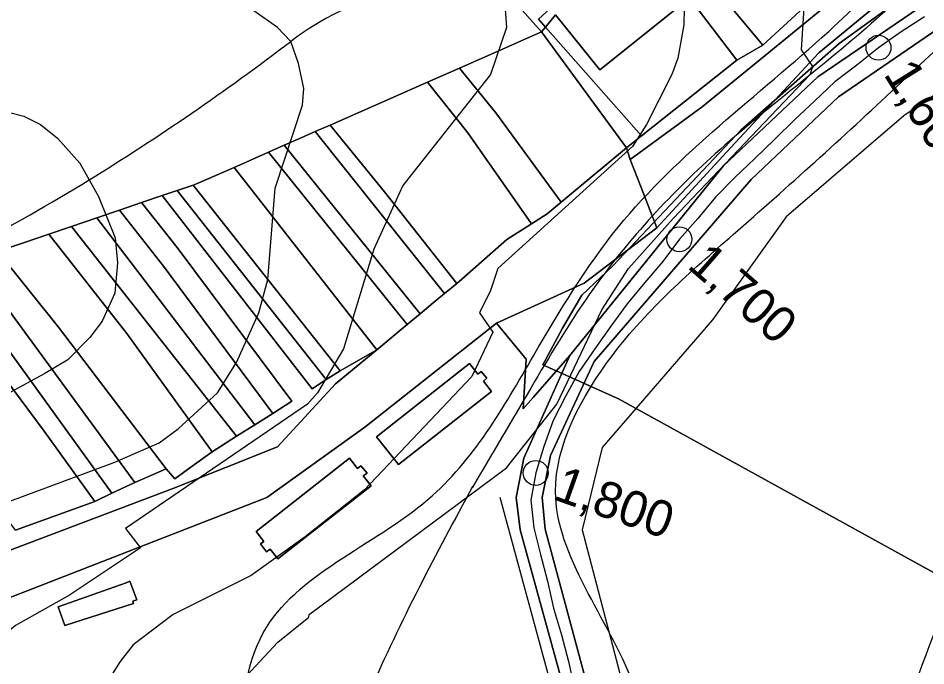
# Model space of a CAD drawing. Extents: x -510989 to -501240, y -1184665 to -1176089.
# Drawn here: x -504942 to -504614, y -1181176.6 to -1180942.6 of the extents above; entities that cross this region are included whole.
import ezdxf

# ---------------------------------------------------------------- set-up
doc = ezdxf.new("R2010")
doc.units = 0
for name, color, linetype in [('lesni_pozemek', 7, 'Continuous'), ('NAVRH_revitalizace_toku', 7, 'Continuous'), ('NAVRH_rozvodnice', 7, 'Continuous'), ('orna_puda', 7, 'Continuous'), ('ostatni_plocha_x_manipulacni_plocha', 7, 'Continuous'), ('ostatni_plocha_x_neplodna_puda', 7, 'Continuous'), ('ostatni_plocha_x_silnice', 7, 'Continuous'), ('ostatni_plocha_x_sportoviste_a_rekr_plocha', 7, 'Continuous'), ('STAV_USES', 7, 'Continuous'), ('STAV_zaplavove_uzemi', 7, 'Continuous'), ('trasovani_toku', 7, 'Continuous'), ('vodni_plocha_x_vodni_tok_v_koryt_prir_n_upr', 7, 'Continuous'), ('vrstevnice_01', 7, 'Continuous'), ('vrstevnice_02', 7, 'Continuous'), ('zastavena_plocha_a_nadvori', 7, 'Continuous')]:
    doc.layers.add(name, color=color, linetype=linetype)

msp = doc.modelspace()

# ---------------------------------------------------------------- linework, layer by layer
at = {"layer": 'lesni_pozemek'}
msp.add_lwpolyline([(-504775.02, -1180922.63), (-504752.9, -1180947.58), (-504771.38, -1180955.72), (-504782.54, -1180960.64), (-504794.06, -1180965.71), (-504829.23, -1180981.2), (-504834.63, -1180983.58), (-504839.79, -1180985.85), (-504845.84, -1180988.52), (-504851.49, -1180991.01), (-504863.93, -1180996.49), (-504877.51, -1181002.47), (-504878.78, -1181002.9), (-504884.56, -1181004.86), (-504890, -1181006.71), (-504897.47, -1181009.24), (-504905.42, -1181011.95), (-504913.53, -1181014.7), (-504922.73, -1181017.82), (-504930.97, -1181020.62), (-504940.12, -1181023.73), (-504949.52, -1181026.92)], dxfattribs=at)
at = {"layer": 'NAVRH_revitalizace_toku'}
for points in [[(-504182.04, -1180792.04), (-504204.87, -1180813.12), (-504441.3, -1180893.49), (-504535.64, -1180920.73), (-504547.6, -1180927.38), (-504622.01, -1180977.87), (-504664.53, -1181014.41), (-504691.11, -1181051.62), (-504730.92, -1181097.66), (-504738.16, -1181127.41), (-504718.87, -1181201.36), (-504687.51, -1181317.93), (-504646.6, -1181475.99), (-504595.04, -1181660.81)], [(-504619.38, -1181665.94), (-504652.45, -1181546.29), (-504699.14, -1181368.28), (-504767.85, -1181115.82)]]:
    msp.add_lwpolyline(points, dxfattribs=at)
at = {"layer": 'NAVRH_rozvodnice'}
for centre, radius, start, end in [((-504781.18, -1181032.78), 102.82, 81.8427, 127.3105), ((-505385.87, -1180239.31), 894.79, 301.65308, 307.31051), ((-505269.53, -1180428.03), 673.1, 293.18985, 301.65308)]:
    msp.add_arc(centre, radius, start, end, dxfattribs=at)
at = {"layer": 'orna_puda'}
for points in [[(-504609.62, -1181654.37), (-504714.66, -1181264.33), (-504714.68, -1181264.25), (-504716.76, -1181256.52), (-504751.58, -1181127.22), (-504752.67, -1181115.82), (-504749.63, -1181100.59), (-504733.91, -1181066.63), (-504677.14, -1181000.88), (-504645.58, -1180971.03), (-504557.05, -1180910.28)], [(-504942.94, -1181127.57), (-504914.26, -1181117.19), (-504908.15, -1181114.19), (-504899.88, -1181110.39), (-504888.48, -1181105.35), (-504885.33, -1181108.96), (-504879.16, -1181104.4), (-504871.86, -1181099.28), (-504863.09, -1181093.58), (-504856.53, -1181089.46), (-504850.02, -1181085.38), (-504843.15, -1181080.96), (-504884.52, -1181025.4), (-504897.47, -1181009.24), (-504890, -1181006.71), (-504835.74, -1181076.52), (-504830.68, -1181073.09), (-504825.69, -1181070.01), (-504812.44, -1181062.36), (-504827.33, -1181074.66), (-504848.34, -1181097.46), (-504885.76, -1181112.45), (-504945.87, -1181135.16)]]:
    msp.add_lwpolyline(points, dxfattribs=at)
for points in [[(-504752.9, -1180947.58), (-504722.23, -1180989.44), (-504735.7, -1181000.67), (-504745.74, -1181009.04), (-504769.45, -1180976.84), (-504782.54, -1180960.64), (-504771.38, -1180955.72)], [(-504782.54, -1180960.64), (-504769.45, -1180976.84), (-504745.74, -1181009.04), (-504750.89, -1181013.33), (-504756.51, -1181016.88), (-504779.57, -1180983.97), (-504794.06, -1180965.71)], [(-504794.06, -1180965.71), (-504779.57, -1180983.97), (-504756.51, -1181016.88), (-504765.42, -1181022.51), (-504781.63, -1181036.9), (-504783.51, -1181038.45), (-504809.57, -1181005.36), (-504829.23, -1180981.2)], [(-504829.23, -1180981.2), (-504809.57, -1181005.36), (-504783.51, -1181038.45), (-504787.94, -1181042.11), (-504834.63, -1180983.58)], [(-504834.63, -1180983.58), (-504787.94, -1181042.11), (-504791.99, -1181045.46), (-504796.71, -1181049.36), (-504845.84, -1180988.52), (-504839.79, -1180985.85)], [(-504845.84, -1180988.52), (-504796.71, -1181049.36), (-504801.38, -1181053.22), (-504851.49, -1180991.01)], [(-504851.49, -1180991.01), (-504801.38, -1181053.22), (-504812.44, -1181062.36), (-504863.93, -1180996.49)], [(-504863.93, -1180996.49), (-504812.44, -1181062.36), (-504825.69, -1181070.01), (-504878.78, -1181002.9), (-504877.51, -1181002.47)], [(-504884.56, -1181004.86), (-504830.68, -1181073.09), (-504835.74, -1181076.52), (-504890, -1181006.71)], [(-504878.78, -1181002.9), (-504825.69, -1181070.01), (-504830.68, -1181073.09), (-504884.56, -1181004.86)], [(-504897.47, -1181009.24), (-504884.52, -1181025.4), (-504843.15, -1181080.96), (-504850.02, -1181085.38), (-504889.51, -1181032.24), (-504905.42, -1181011.95)], [(-504913.53, -1181014.7), (-504856.53, -1181089.46), (-504863.09, -1181093.58), (-504922.73, -1181017.82)], [(-504905.42, -1181011.95), (-504889.51, -1181032.24), (-504850.02, -1181085.38), (-504856.53, -1181089.46), (-504913.53, -1181014.7)], [(-504922.73, -1181017.82), (-504863.09, -1181093.58), (-504871.86, -1181099.28), (-504902.76, -1181056.48), (-504930.97, -1181020.62)], [(-504930.97, -1181020.62), (-504902.76, -1181056.48), (-504871.86, -1181099.28), (-504879.16, -1181104.4), (-504885.33, -1181108.96), (-504888.48, -1181105.35), (-504927.37, -1181054.18), (-504949.52, -1181026.92), (-504940.12, -1181023.73)], [(-504949.52, -1181026.92), (-504927.37, -1181054.18), (-504888.48, -1181105.35), (-504899.88, -1181110.39), (-504958.78, -1181030.06)], [(-504958.78, -1181030.06), (-504899.88, -1181110.39), (-504908.15, -1181114.19), (-504964.75, -1181035.96)], [(-504964.75, -1181035.96), (-504908.15, -1181114.19), (-504914.26, -1181117.19), (-504932.57, -1181091.77), (-504970.16, -1181041.3)], [(-504970.16, -1181041.3), (-504932.57, -1181091.77), (-504914.26, -1181117.19), (-504942.94, -1181127.57), (-504991.43, -1181062.3)]]:
    msp.add_lwpolyline(points, close=True, dxfattribs=at)
at = {"layer": 'ostatni_plocha_x_manipulacni_plocha'}
msp.add_lwpolyline([(-504669.28, -1180908.4), (-504646.56, -1180892.33), (-504625.33, -1180910.8), (-504628.44, -1180912.7), (-504642.21, -1180924.36), (-504649.15, -1180930.38), (-504672.94, -1180952.33), (-504688.81, -1180933.14), (-504690.04, -1180930.4), (-504690.56, -1180927.53), (-504689.67, -1180924.68), (-504688.1, -1180922.19), (-504674.05, -1180911.16)], close=True, dxfattribs=at)
msp.add_lwpolyline([(-504688.81, -1180933.14), (-504672.94, -1180952.33), (-504682.35, -1180957.74), (-504699.48, -1180935.25), (-504731.88, -1180961.27), (-504747.81, -1180941.41), (-504751.48, -1180945.85), (-504754, -1180943), (-504718, -1180910)], dxfattribs=at)
at = {"layer": 'ostatni_plocha_x_neplodna_puda'}
msp.add_lwpolyline([(-504582.6, -1180900.93), (-504574.16, -1180900.62), (-504566.19, -1180904.56), (-504653.08, -1180963.75), (-504687.23, -1180996.05), (-504742.72, -1181064.52), (-504755.9, -1181079.67), (-504759.48, -1181083.79), (-504758.44, -1181065.74), (-504769.19, -1181052.84), (-504737.43, -1181038.27), (-504711.26, -1181018.31), (-504686.07, -1180991.03), (-504652.66, -1180955.07), (-504600.25, -1180911.88)], close=True, dxfattribs=at)
at = {"layer": 'ostatni_plocha_x_silnice'}
for points in [[(-504600.25, -1180911.88), (-504652.66, -1180955.07), (-504686.07, -1180991.03), (-504711.26, -1181018.31), (-504716.94, -1181003.71), (-504719.55, -1180997), (-504720.83, -1180993.69), (-504694.88, -1180974.6), (-504670.77, -1180954.95), (-504614.89, -1180909.19), (-504613.27, -1180908.14), (-504617.64, -1180907.65), (-504616.22, -1180905.23), (-504600.67, -1180895.84)], [(-504945.87, -1181135.16), (-504885.76, -1181112.45), (-504848.34, -1181097.46), (-504827.33, -1181074.66), (-504812.44, -1181062.36), (-504801.38, -1181053.22), (-504796.71, -1181049.36), (-504791.99, -1181045.46), (-504787.94, -1181042.11), (-504783.51, -1181038.45), (-504781.63, -1181036.9), (-504765.42, -1181022.51), (-504756.51, -1181016.88), (-504750.89, -1181013.33), (-504745.74, -1181009.04), (-504735.7, -1181000.67), (-504722.23, -1180989.44), (-504720.83, -1180993.69), (-504719.55, -1180997), (-504716.94, -1181003.71), (-504711.26, -1181018.31), (-504737.43, -1181038.27), (-504769.19, -1181052.84), (-504816.79, -1181090.4), (-504852.19, -1181115.81), (-504959.56, -1181157.6)]]:
    msp.add_lwpolyline(points, dxfattribs=at)
at = {"layer": 'ostatni_plocha_x_sportoviste_a_rekr_plocha'}
for points in [[(-504808, -1180882.51), (-504725, -1180870), (-504718, -1180910), (-504754, -1180943), (-504751.48, -1180945.85), (-504752.9, -1180947.58), (-504775.02, -1180922.63), (-504813.81, -1180883.39)], [(-504616.22, -1180905.23), (-504617.64, -1180907.65), (-504613.27, -1180908.14), (-504614.89, -1180909.19), (-504670.77, -1180954.95), (-504694.88, -1180974.6), (-504720.83, -1180993.69), (-504722.23, -1180989.44), (-504716.78, -1180985.11), (-504682.35, -1180957.74), (-504672.94, -1180952.33), (-504649.15, -1180930.38), (-504642.21, -1180924.36), (-504628.44, -1180912.7), (-504625.33, -1180910.8)], [(-504775.91, -1181071.15), (-504778.88, -1181067.35), (-504812.53, -1181093.83), (-504804.63, -1181103.82), (-504771, -1181077.43), (-504773.91, -1181073.71), (-504772.62, -1181072.71), (-504774.74, -1181070.23)], [(-504818.23, -1181104.36), (-504819.38, -1181105.25), (-504822.22, -1181101.56), (-504856, -1181127.99), (-504853.24, -1181131.6), (-504854.48, -1181132.56), (-504852.28, -1181135.34), (-504850.98, -1181134.47), (-504848.17, -1181137.97), (-504814.5, -1181111.6), (-504817.28, -1181107.99), (-504815.94, -1181106.96)], [(-504901.63, -1181145.94), (-504903.01, -1181146.58), (-504927.59, -1181155.21), (-504925.18, -1181161.97), (-504900.33, -1181154.06), (-504900.6, -1181153.27), (-504899.1, -1181152.68)]]:
    msp.add_lwpolyline(points, close=True, dxfattribs=at)
msp.add_lwpolyline([(-504959.56, -1181157.6), (-504852.19, -1181115.81), (-504816.79, -1181090.4), (-504769.19, -1181052.84), (-504758.44, -1181065.74), (-504759.48, -1181083.79), (-504755.9, -1181079.67), (-504742.72, -1181064.52), (-504759.3, -1181101.6), (-504762.01, -1181115.76), (-504760.66, -1181127.46), (-504726.66, -1181250.72)], dxfattribs=at)
at = {"layer": 'STAV_USES'}
for p, q in [((-504645.34, -1180951.73), (-504609.16, -1180925.58)), ((-504609.16, -1180925.58), (-504645.34, -1180951.73)), ((-504680.9, -1180983.06), (-504645.34, -1180951.73)), ((-504645.34, -1180951.73), (-504680.9, -1180983.06)), ((-504704.31, -1181008), (-504680.9, -1180983.06)), ((-504680.9, -1180983.06), (-504704.31, -1181008)), ((-504727.11, -1181032.02), (-504704.31, -1181008)), ((-504704.31, -1181008), (-504727.11, -1181032.02)), ((-504738.36, -1181042.67), (-504727.11, -1181032.02)), ((-504727.11, -1181032.02), (-504738.36, -1181042.67)), ((-504745.35, -1181054.53), (-504738.36, -1181042.67)), ((-504738.36, -1181042.67), (-504745.35, -1181054.53)), ((-504752.39, -1181067.83), (-504745.35, -1181054.53)), ((-504745.35, -1181054.53), (-504752.39, -1181067.83)), ((-504725.03, -1181080.14), (-504752.39, -1181067.83)), ((-504752.39, -1181067.83), (-504725.03, -1181080.14)), ((-504608.86, -1181144.24), (-504725.03, -1181080.14)), ((-504725.03, -1181080.14), (-504608.86, -1181144.24))]:
    msp.add_line(p, q, dxfattribs=at)
at = {"layer": 'STAV_zaplavove_uzemi'}
for points in [[(-503691.1, -1180709.63), (-503698.14, -1180689.92), (-503726.29, -1180661.77), (-503758.67, -1180635.02), (-503793.87, -1180613.9), (-503848.78, -1180591.37), (-503885.38, -1180575.88), (-503937.22, -1180564.11), (-503952.58, -1180564.11), (-503964.1, -1180580.75), (-503962.82, -1180602.51), (-503964.1, -1180625.54), (-503990.97, -1180635.78), (-504028.09, -1180635.78), (-504080.57, -1180656.26), (-504118.96, -1180675.46), (-504153.52, -1180702.34), (-504177.84, -1180745.85), (-504193.2, -1180768.89), (-504226.47, -1180789.37), (-504318.63, -1180820.09), (-504383.9, -1180844.41), (-504463.25, -1180867.44), (-504524.69, -1180885.36), (-504582.26, -1180902.78), (-504631.98, -1180942.98), (-504690.15, -1180991.64), (-504735.64, -1181042.41), (-504756.79, -1181076.26), (-504777.95, -1181112.22)], [(-504594.17, -1181642.09), (-504629.77, -1181535.28), (-504650.39, -1181443.46), (-504674.75, -1181355.39), (-504706.6, -1181265.44), (-504719.72, -1181182.99), (-504747.83, -1181113.66), (-504727.29, -1181064.42), (-504683.65, -1181020.77), (-504624.52, -1180967.28), (-504575.24, -1180927.85), (-504544.27, -1180915.18), (-504445.72, -1180881.39), (-504404.89, -1180867.31), (-504292.26, -1180829.3), (-504179.63, -1180791.29), (-504099.38, -1180734.98), (-504020.54, -1180698.37), (-503957.18, -1180675.84), (-503893.83, -1180664.58), (-503865.67, -1180678.66), (-503817.8, -1180689.92), (-503788.24, -1180689.92), (-503764.3, -1180695.55), (-503736.15, -1180687.11), (-503717.85, -1180698.37), (-503716.44, -1180708.23)], [(-502250.32, -1184002.61), (-502355.07, -1183875.41), (-502442.37, -1183790.61), (-502477.29, -1183700.82), (-502532.16, -1183578.61), (-502567.08, -1183448.91), (-502626.05, -1183402.34), (-502705.41, -1183380.59), (-502814.2, -1183349.87), (-502882.03, -1183297.39), (-502931.95, -1183237.24), (-503042.02, -1183107.97), (-503139.64, -1183018.94), (-503222.14, -1182957.59), (-503308.56, -1182839.96), (-503316.24, -1182784.92), (-503330.32, -1182756.77), (-503348.24, -1182719.65), (-503334.16, -1182651.82), (-503323.92, -1182595.5), (-503313.68, -1182526.39), (-503294.1, -1182480.5), (-503251.86, -1182396.03), (-503229.34, -1182314.37), (-503216.1, -1182227.15), (-503242.43, -1182174.5), (-503271.86, -1182129.59), (-503287.34, -1182081.58), (-503343.88, -1182028.1), (-503361.79, -1182008.91), (-503396.35, -1181952.59), (-503442.43, -1181933.39), (-503497.46, -1181888.6), (-503525.62, -1181860.44), (-503528.18, -1181837.4), (-503548.66, -1181767.01), (-503558.9, -1181729.89), (-503576.82, -1181682.53), (-503578.1, -1181621.1), (-503567.86, -1181572.46), (-503552.5, -1181536.63), (-503538.04, -1181458.36), (-503518.33, -1181411.9), (-503509.88, -1181341.51), (-503497.21, -1181207.63), (-503499.77, -1181097.56), (-503498.02, -1181031.35), (-503510.82, -1180970.85), (-503549.22, -1180952.23), (-503571.32, -1180940.6), (-503605.07, -1180937.11), (-503651.61, -1180939.44), (-503671.39, -1180917.33), (-503679.53, -1180892.89), (-503713.27, -1180871.95), (-503727.24, -1180859.15), (-503734.22, -1180833.55), (-503728.4, -1180799.81), (-503741.2, -1180770.72), (-503722.82, -1180725.17), (-503721.54, -1180703.41), (-503731.78, -1180697.01), (-503767.61, -1180699.57), (-503790.65, -1180697.01), (-503817.53, -1180697.01), (-503861.04, -1180686.77), (-503889.2, -1180675.25), (-503900.72, -1180668.85), (-503953.2, -1180679.09), (-503997.99, -1180697.01), (-504063.27, -1180722.61), (-504109.34, -1180749.49), (-504142.62, -1180776.36), (-504177.18, -1180796.84), (-504211.73, -1180817.32), (-504414.98, -1180961.5), (-504472.7, -1180998.11), (-504544.51, -1181068.5), (-504600.82, -1181143.12), (-504621.94, -1181196.62), (-504641.65, -1181267.01), (-504660.25, -1181350.62), (-504634.7, -1181398.32), (-504617.66, -1181447.72), (-504600.62, -1181492.01), (-504587, -1181548.23), (-504592.11, -1181628.29), (-504569.96, -1181682.81), (-504568.26, -1181664.07), (-504554.63, -1181621.48), (-504547.82, -1181597.63)], [(-504826.46, -1182247.73), (-504827.62, -1182204.68), (-504817.15, -1182165.12), (-504791.55, -1182113.93), (-504727.56, -1182034.81), (-504708.94, -1182017.35), (-504669.38, -1181991.76), (-504649.6, -1181961.5), (-504628.66, -1181917.29), (-504601.9, -1181867.26), (-504597.24, -1181809.08), (-504585.16, -1181766.79), (-504596.8, -1181741.4), (-504604.2, -1181726.59), (-504633.82, -1181658.9), (-504646.51, -1181600.72), (-504660.26, -1181556.29), (-504751.04, -1181459.08), (-504798.4, -1181384.84), (-504826.55, -1181347.73), (-504862.39, -1181315.73), (-504866.23, -1181265.81), (-504862.39, -1181205.66), (-504853.43, -1181164.7), (-504793.92, -1181116.47), (-504755.84, -1181064.64), (-504725.17, -1181018.1), (-504649.01, -1180947.23), (-504594, -1180900.69), (-504545.35, -1180879.53), (-504377.38, -1180832.83), (-504317.01, -1180808.36), (-504368.93, -1180802.59), (-504426.63, -1180826.63), (-504542.02, -1180859.32)], [(-504777.81, -1181111.78), (-504815.29, -1181186.74), (-504828.41, -1181242.96), (-504796.55, -1181306.67), (-504764.69, -1181361.01), (-504723.47, -1181428.47), (-504674.75, -1181510.92), (-504648.51, -1181582.13), (-504622.28, -1181672.07)]]:
    msp.add_spline(points, degree=3, dxfattribs=at)
at = {"layer": 'trasovani_toku'}
for p, q in [((-504614.57, -1180942.09), (-504622.95, -1180947.54)), ((-504622.95, -1180947.54), (-504631.14, -1180953.29)), ((-504631.14, -1180953.29), (-504638.94, -1180959.54)), ((-504638.94, -1180959.54), (-504646.92, -1180965.57)), ((-504646.92, -1180965.57), (-504654.19, -1180972.43)), ((-504654.19, -1180972.43), (-504661.47, -1180979.29)), ((-504661.47, -1180979.29), (-504668.63, -1180986.28)), ((-504668.63, -1180986.28), (-504675.78, -1180993.26)), ((-504675.78, -1180993.26), (-504683.06, -1181000.12)), ((-504683.06, -1181000.12), (-504690, -1181007.32)), ((-504690, -1181007.32), (-504696.44, -1181014.97)), ((-504696.44, -1181014.97), (-504703.06, -1181022.47)), ((-504703.06, -1181022.47), (-504709.05, -1181030.47)), ((-504709.05, -1181030.47), (-504715.58, -1181038.05)), ((-504715.58, -1181038.05), (-504721.93, -1181045.77)), ((-504721.93, -1181045.77), (-504727.87, -1181053.82)), ((-504727.87, -1181053.82), (-504733.57, -1181062.03)), ((-504733.57, -1181062.03), (-504739.24, -1181070.27)), ((-504739.24, -1181070.27), (-504744.07, -1181079.02)), ((-504744.07, -1181079.02), (-504748.67, -1181087.91)), ((-504748.67, -1181087.91), (-504752.03, -1181097.33)), ((-504752.03, -1181097.33), (-504754.99, -1181106.88)), ((-504754.99, -1181106.88), (-504756.71, -1181116.73)), ((-504756.71, -1181116.73), (-504755.7, -1181126.68)), ((-504755.7, -1181126.68), (-504753.3, -1181136.39)), ((-504753.3, -1181136.39), (-504750.71, -1181146.04)), ((-504750.71, -1181146.04), (-504748.53, -1181155.8)), ((-504748.53, -1181155.8), (-504745.65, -1181165.38)), ((-504745.65, -1181165.38), (-504743.16, -1181175.06)), ((-504743.16, -1181175.06), (-504740.99, -1181184.83))]:
    msp.add_line(p, q, dxfattribs=at)
for centre in [(-504631.14, -1180953.29), (-504703.06, -1181022.47), (-504754.99, -1181106.88)]:
    msp.add_circle(centre, 4.5, dxfattribs=at)
at = {"layer": 'vodni_plocha_x_vodni_tok_v_koryt_prir_n_upr'}
for points in [[(-504608.12, -1181659.96), (-504614.86, -1181665.13), (-504632.61, -1181599.34), (-504645.61, -1181551.13), (-504655.26, -1181515.38), (-504662.52, -1181488.46), (-504712.86, -1181301.83), (-504721.2, -1181270.94), (-504723.29, -1181263.22), (-504723.31, -1181263.13), (-504725.66, -1181254.39), (-504726.28, -1181252.1), (-504726.66, -1181250.72), (-504760.66, -1181127.46), (-504762.01, -1181115.76), (-504759.3, -1181101.6), (-504742.72, -1181064.52), (-504687.23, -1180996.05), (-504653.08, -1180963.75), (-504566.19, -1180904.56)], [(-504557.05, -1180910.28), (-504645.58, -1180971.03), (-504677.14, -1181000.88), (-504733.91, -1181066.63), (-504749.63, -1181100.59), (-504752.67, -1181115.82), (-504751.58, -1181127.22), (-504716.76, -1181256.52), (-504714.68, -1181264.25), (-504714.66, -1181264.33), (-504609.62, -1181654.37)]]:
    msp.add_lwpolyline(points, dxfattribs=at)
at = {"layer": 'vrstevnice_01'}
for points in [[(-504766.59, -1180931), (-504765.59, -1180946), (-504771.31, -1180963), (-504803, -1181003), (-504813.5, -1181026), (-504824.41, -1181062), (-504833.81, -1181078), (-504837.5, -1181082), (-504903.19, -1181127), (-504897.81, -1181134)], [(-504865.91, -1181187), (-504848.19, -1181168), (-504836.91, -1181159), (-504836.81, -1181158), (-504765.59, -1181105), (-504747.31, -1181082), (-504731.09, -1181048), (-504721.41, -1181033), (-504705.31, -1181015), (-504655.81, -1180963), (-504654.81, -1180960), (-504659, -1180954), (-504657.69, -1180933)], [(-504951.81, -1180975), (-504940, -1180978), (-504933.91, -1180981), (-504927.81, -1180986), (-504919.69, -1180995), (-504912.91, -1181007), (-504907, -1181022), (-504906.09, -1181031), (-504907.09, -1181042), (-504911.69, -1181052), (-504916.09, -1181058), (-504924, -1181066), (-504932.31, -1181071), (-504976.59, -1181095)], [(-504897.81, -1181134), (-504923.41, -1181151), (-504942.91, -1181162), (-504951.5, -1181169), (-504962.69, -1181190), (-504969.31, -1181221), (-504971.59, -1181244), (-504972.81, -1181276), (-504968.5, -1181322), (-504967.21, -1181373.59)]]:
    msp.add_lwpolyline(points, dxfattribs=at)
at = {"layer": 'vrstevnice_02'}
for points in [[(-504701.41, -1180939), (-504701.5, -1180945), (-504703.69, -1180957), (-504705.81, -1180963), (-504714.91, -1180981), (-504720, -1180989), (-504768.69, -1181033), (-504771.31, -1181041), (-504775.31, -1181049), (-504770.5, -1181056), (-504778.09, -1181072), (-504816.91, -1181113), (-504838.31, -1181130), (-504857.81, -1181144), (-504886, -1181158), (-504900.5, -1181169), (-504905.19, -1181175), (-504916.41, -1181193), (-504923, -1181210), (-504926.81, -1181222), (-504930.59, -1181241), (-504933.09, -1181261), (-504934.31, -1181288)], [(-504963.59, -1181124), (-504907.09, -1181103), (-504891, -1181096), (-504884.19, -1181091), (-504870, -1181078), (-504863.09, -1181067), (-504855.09, -1181049), (-504851.81, -1181037), (-504849.19, -1181004), (-504839.31, -1180974), (-504838.81, -1180968), (-504840.69, -1180959), (-504843.5, -1180951), (-504848.31, -1180946), (-504856.81, -1180940)]]:
    msp.add_lwpolyline(points, dxfattribs=at)
at = {"layer": 'zastavena_plocha_a_nadvori'}
for points in [[(-504751.48, -1180945.85), (-504747.81, -1180941.41), (-504731.88, -1180961.27), (-504699.48, -1180935.25), (-504682.35, -1180957.74), (-504716.78, -1180985.11)], [(-504752.9, -1180947.58), (-504751.48, -1180945.85), (-504716.78, -1180985.11), (-504722.23, -1180989.44)], [(-504775.91, -1181071.15), (-504774.74, -1181070.23), (-504772.62, -1181072.71), (-504773.91, -1181073.71), (-504771, -1181077.43), (-504804.63, -1181103.82), (-504812.53, -1181093.83), (-504778.88, -1181067.35)], [(-504818.23, -1181104.36), (-504815.94, -1181106.96), (-504817.28, -1181107.99), (-504814.5, -1181111.6), (-504848.17, -1181137.97), (-504850.98, -1181134.47), (-504852.28, -1181135.34), (-504854.48, -1181132.56), (-504853.24, -1181131.6), (-504856, -1181127.99), (-504822.22, -1181101.56), (-504819.38, -1181105.25)], [(-504901.63, -1181145.94), (-504899.1, -1181152.68), (-504900.6, -1181153.27), (-504900.33, -1181154.06), (-504925.18, -1181161.97), (-504927.59, -1181155.21), (-504903.01, -1181146.58)]]:
    msp.add_lwpolyline(points, close=True, dxfattribs=at)

# ---------------------------------------------------------------- texts
at = {"layer": 'trasovani_toku'}
for s, rotation, p in [('1,600', 301.9946, (-504629.51, -1180962.82)), ('1,700', 318.9063, (-504700.66, -1181032.52)), ('1,800', 340.4558, (-504749.07, -1181116.3))]:
    msp.add_text(s, height=13, rotation=rotation, dxfattribs=at).set_placement(p)

doc.saveas('drawing.dxf')
